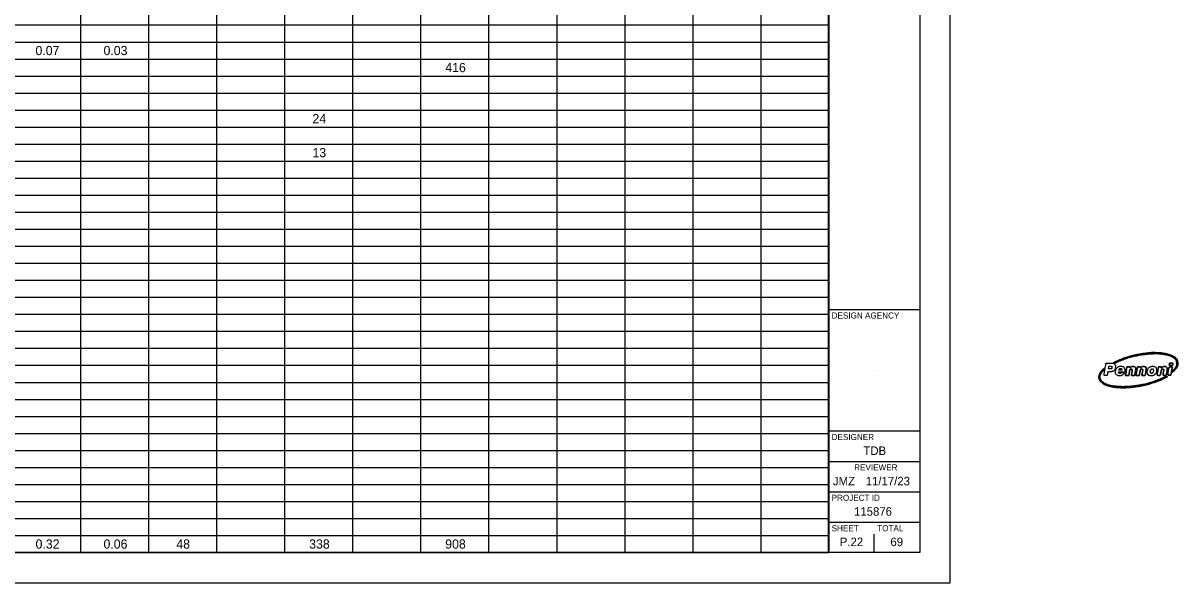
# Model space of a CAD drawing. Extents: x -0.1 to 37.6, y 0 to 22.
# Drawn here: x 18.61 to 37.63, y -0.02 to 9.19 of the extents above; entities that cross this region are included whole.
import ezdxf

# ---------------------------------------------------------------- set-up
doc = ezdxf.new("R2010")
doc.units = 0
for name, color, linetype in [('Default', 7, 'Continuous'), ('SH_Border', 7, 'Continuous'), ('SH_Cut_Line', 7, 'Continuous'), ('SH_Data', 7, 'Continuous')]:
    doc.layers.add(name, color=color, linetype=linetype)

msp = doc.modelspace()

# ---------------------------------------------------------------- linework, layer by layer
at = {"layer": 'Default'}
for p, q in [((19.559, 21.475), (19.559, 0.475)), ((20.679, 21.475), (20.679, 0.475)), ((21.799, 21.475), (21.799, 0.475)), ((22.919, 21.475), (22.919, 0.475)), ((24.039, 21.475), (24.039, 0.475)), ((25.159, 21.475), (25.159, 0.475)), ((26.279, 21.475), (26.279, 0.475)), ((27.399, 21.475), (27.399, 0.475)), ((28.519, 21.475), (28.519, 0.475)), ((29.639, 21.475), (29.639, 0.475)), ((30.759, 21.475), (30.759, 0.475)), ((31.879, 21.475), (31.879, 0.475)), ((1.376, 9.155), (31.879, 9.155)), ((1.376, 8.875), (31.879, 8.875)), ((1.376, 8.595), (31.879, 8.595)), ((1.376, 8.315), (31.879, 8.315)), ((1.376, 8.035), (31.879, 8.035)), ((1.376, 7.755), (31.879, 7.755)), ((1.376, 7.475), (31.879, 7.475)), ((1.376, 7.195), (31.879, 7.195)), ((1.376, 6.915), (31.879, 6.915)), ((1.376, 6.635), (31.879, 6.635)), ((1.376, 6.355), (31.879, 6.355)), ((1.376, 6.075), (31.879, 6.075)), ((1.376, 5.795), (31.879, 5.795)), ((1.376, 5.515), (31.879, 5.515)), ((1.376, 5.235), (31.879, 5.235)), ((1.376, 4.955), (31.879, 4.955)), ((1.376, 4.675), (31.879, 4.675)), ((1.376, 4.395), (31.879, 4.395)), ((1.376, 4.115), (31.879, 4.115)), ((1.376, 3.835), (31.879, 3.835)), ((1.376, 3.555), (31.879, 3.555)), ((1.376, 3.275), (31.879, 3.275)), ((1.376, 2.995), (31.879, 2.995)), ((1.376, 2.715), (31.879, 2.715)), ((1.376, 2.435), (31.879, 2.435)), ((1.376, 2.155), (31.879, 2.155)), ((1.376, 1.875), (31.879, 1.875)), ((1.376, 1.595), (31.879, 1.595)), ((1.376, 1.315), (31.879, 1.315)), ((1.376, 1.035), (31.879, 1.035)), ((1.376, 0.755), (31.879, 0.755)), ((1.376, 0.475), (31.879, 0.475))]:
    msp.add_line(p, q, dxfattribs=at)
at = {"layer": 'SH_Border'}
for p, q in [((31.876, 0.475), (31.876, 21.475)), ((31.876, 4.475), (33.376, 4.475)), ((36.706, 3.478), (36.656, 3.478)), ((31.876, 2.475), (33.376, 2.475)), ((31.876, 1.975), (33.376, 1.975)), ((31.876, 1.475), (33.376, 1.475)), ((31.876, 0.975), (33.376, 0.975))]:
    msp.add_line(p, q, dxfattribs=at)
msp.add_lwpolyline([(1.376, 21.475), (33.376, 21.475), (33.376, 0.475), (1.376, 0.475)], close=True, dxfattribs=at)
for points, degree in [([(36.565, 3.596), (36.572, 3.594), (36.578, 3.591), (36.584, 3.59), (36.586, 3.589), (36.589, 3.589), (36.591, 3.59), (36.62, 3.604), (36.648, 3.618), (36.677, 3.63), (36.718, 3.648), (36.761, 3.663), (36.804, 3.676), (36.846, 3.689), (36.888, 3.7), (36.931, 3.709), (36.971, 3.718), (37.011, 3.726), (37.051, 3.731), (37.083, 3.735), (37.115, 3.739), (37.147, 3.742), (37.173, 3.744), (37.198, 3.745), (37.223, 3.746), (37.278, 3.748), (37.333, 3.745), (37.388, 3.737), (37.417, 3.733), (37.447, 3.727), (37.475, 3.717), (37.511, 3.706), (37.544, 3.692), (37.572, 3.666), (37.588, 3.653), (37.599, 3.636), (37.604, 3.616), (37.609, 3.599), (37.611, 3.582), (37.608, 3.564), (37.604, 3.544), (37.594, 3.527), (37.582, 3.511), (37.57, 3.496), (37.556, 3.483), (37.541, 3.47), (37.54, 3.469), (37.538, 3.467), (37.537, 3.465), (37.536, 3.46), (37.535, 3.454), (37.534, 3.448), (37.534, 3.446), (37.534, 3.444), (37.533, 3.44), (37.557, 3.46), (37.58, 3.48), (37.598, 3.504), (37.607, 3.515), (37.615, 3.528), (37.62, 3.541), (37.627, 3.56), (37.627, 3.579), (37.625, 3.598), (37.621, 3.633), (37.605, 3.66), (37.579, 3.683), (37.555, 3.703), (37.528, 3.716), (37.499, 3.727), (37.461, 3.741), (37.423, 3.749), (37.384, 3.754), (37.349, 3.759), (37.314, 3.762), (37.279, 3.763), (37.222, 3.765), (37.166, 3.762), (37.11, 3.756), (37.079, 3.752), (37.048, 3.748), (37.017, 3.743), (36.972, 3.736), (36.927, 3.727), (36.883, 3.715), (36.822, 3.7), (36.763, 3.682), (36.705, 3.66), (36.664, 3.644), (36.624, 3.626), (36.585, 3.606), (36.578, 3.603), (36.572, 3.6), (36.565, 3.596)], 3), ([(36.565, 3.596), (36.572, 3.6), (36.578, 3.603), (36.585, 3.606), (36.624, 3.626), (36.664, 3.644), (36.705, 3.66), (36.763, 3.682), (36.822, 3.7), (36.883, 3.715), (36.927, 3.727), (36.972, 3.736), (37.017, 3.743), (37.048, 3.748), (37.079, 3.752), (37.11, 3.756), (37.166, 3.762), (37.222, 3.765), (37.279, 3.763), (37.314, 3.762), (37.349, 3.759), (37.384, 3.754), (37.423, 3.749), (37.461, 3.741), (37.499, 3.727), (37.528, 3.716), (37.555, 3.703), (37.579, 3.683), (37.605, 3.66), (37.621, 3.633), (37.625, 3.598), (37.627, 3.579), (37.627, 3.56), (37.62, 3.541), (37.615, 3.528), (37.607, 3.515), (37.598, 3.504), (37.58, 3.48), (37.557, 3.46), (37.533, 3.44), (37.534, 3.444), (37.534, 3.446), (37.534, 3.448), (37.535, 3.454), (37.536, 3.46), (37.537, 3.465), (37.538, 3.467), (37.54, 3.469), (37.541, 3.47), (37.556, 3.483), (37.57, 3.496), (37.582, 3.511), (37.594, 3.527), (37.604, 3.544), (37.608, 3.564), (37.611, 3.582), (37.609, 3.599), (37.604, 3.616), (37.599, 3.636), (37.588, 3.653), (37.572, 3.666), (37.544, 3.692), (37.511, 3.706), (37.475, 3.717), (37.447, 3.727), (37.417, 3.733), (37.388, 3.737), (37.333, 3.745), (37.278, 3.748), (37.223, 3.746), (37.198, 3.745), (37.173, 3.744), (37.147, 3.742), (37.115, 3.739), (37.083, 3.735), (37.051, 3.731), (37.011, 3.726), (36.971, 3.718), (36.931, 3.709), (36.888, 3.7), (36.846, 3.689), (36.804, 3.676), (36.761, 3.663), (36.718, 3.648), (36.677, 3.63), (36.648, 3.618), (36.62, 3.604), (36.591, 3.59), (36.589, 3.589), (36.586, 3.589), (36.584, 3.59), (36.578, 3.591), (36.572, 3.594), (36.565, 3.596)], 3), ([(37.454, 3.367), (37.453, 3.367), (37.453, 3.368), (37.453, 3.368), (37.443, 3.368), (37.433, 3.368), (37.423, 3.368), (37.421, 3.368), (37.418, 3.367), (37.416, 3.366), (37.379, 3.347), (37.341, 3.33), (37.302, 3.315), (37.244, 3.292), (37.184, 3.273), (37.124, 3.258), (37.081, 3.246), (37.038, 3.237), (36.994, 3.229), (36.969, 3.225), (36.944, 3.221), (36.92, 3.218), (36.894, 3.214), (36.868, 3.211), (36.843, 3.209), (36.819, 3.207), (36.794, 3.205), (36.77, 3.205), (36.742, 3.204), (36.714, 3.203), (36.686, 3.205), (36.655, 3.206), (36.624, 3.208), (36.593, 3.211), (36.555, 3.215), (36.517, 3.223), (36.481, 3.234), (36.449, 3.244), (36.419, 3.257), (36.392, 3.277), (36.376, 3.289), (36.362, 3.304), (36.353, 3.323), (36.34, 3.349), (36.342, 3.375), (36.352, 3.402), (36.361, 3.425), (36.375, 3.445), (36.392, 3.463), (36.398, 3.469), (36.403, 3.475), (36.403, 3.484), (36.404, 3.489), (36.405, 3.495), (36.406, 3.501), (36.405, 3.5), (36.404, 3.5), (36.403, 3.499), (36.394, 3.489), (36.384, 3.48), (36.375, 3.469), (36.356, 3.447), (36.34, 3.423), (36.332, 3.394), (36.327, 3.377), (36.326, 3.36), (36.329, 3.343), (36.334, 3.316), (36.348, 3.294), (36.368, 3.276), (36.39, 3.255), (36.417, 3.241), (36.445, 3.229), (36.492, 3.21), (36.542, 3.2), (36.592, 3.194), (36.623, 3.191), (36.654, 3.189), (36.685, 3.187), (36.727, 3.186), (36.769, 3.186), (36.812, 3.19), (36.846, 3.192), (36.88, 3.196), (36.914, 3.2), (36.945, 3.204), (36.976, 3.209), (37.006, 3.214), (37.06, 3.224), (37.114, 3.236), (37.167, 3.252), (37.212, 3.264), (37.257, 3.279), (37.301, 3.296), (37.344, 3.313), (37.386, 3.331), (37.427, 3.353), (37.436, 3.357), (37.445, 3.362), (37.454, 3.367)], 3), ([(37.454, 3.367), (37.445, 3.362), (37.436, 3.357), (37.427, 3.353), (37.386, 3.331), (37.344, 3.313), (37.301, 3.296), (37.257, 3.279), (37.212, 3.264), (37.167, 3.252), (37.114, 3.236), (37.06, 3.224), (37.006, 3.214), (36.976, 3.209), (36.945, 3.204), (36.914, 3.2), (36.88, 3.196), (36.846, 3.192), (36.812, 3.19), (36.769, 3.186), (36.727, 3.186), (36.685, 3.187), (36.654, 3.189), (36.623, 3.191), (36.592, 3.194), (36.542, 3.2), (36.492, 3.21), (36.445, 3.229), (36.417, 3.241), (36.39, 3.255), (36.368, 3.276), (36.348, 3.294), (36.334, 3.316), (36.329, 3.343), (36.326, 3.36), (36.327, 3.377), (36.332, 3.394), (36.34, 3.423), (36.356, 3.447), (36.375, 3.469), (36.384, 3.48), (36.394, 3.489), (36.403, 3.499), (36.404, 3.5), (36.405, 3.5), (36.406, 3.501), (36.405, 3.495), (36.404, 3.489), (36.403, 3.484), (36.403, 3.475), (36.398, 3.469), (36.392, 3.463), (36.375, 3.445), (36.361, 3.425), (36.352, 3.402), (36.342, 3.375), (36.34, 3.349), (36.353, 3.323), (36.362, 3.304), (36.376, 3.289), (36.392, 3.277), (36.419, 3.257), (36.449, 3.244), (36.481, 3.234), (36.517, 3.223), (36.555, 3.215), (36.593, 3.211), (36.624, 3.208), (36.655, 3.206), (36.686, 3.205), (36.714, 3.203), (36.742, 3.204), (36.77, 3.205), (36.794, 3.205), (36.819, 3.207), (36.843, 3.209), (36.868, 3.211), (36.894, 3.214), (36.92, 3.218), (36.944, 3.221), (36.969, 3.225), (36.994, 3.229), (37.038, 3.237), (37.081, 3.246), (37.124, 3.258), (37.184, 3.273), (37.244, 3.292), (37.302, 3.315), (37.341, 3.33), (37.379, 3.347), (37.416, 3.366), (37.418, 3.367), (37.421, 3.368), (37.423, 3.368), (37.433, 3.368), (37.443, 3.368), (37.453, 3.368), (37.453, 3.368), (37.453, 3.367), (37.454, 3.367)], 3), ([(36.577, 3.577), (36.564, 3.583), (36.551, 3.585), (36.537, 3.585), (36.505, 3.586), (36.474, 3.585), (36.442, 3.586), (36.44, 3.586), (36.439, 3.585), (36.438, 3.583), (36.435, 3.561), (36.431, 3.54), (36.427, 3.518), (36.421, 3.484), (36.415, 3.449), (36.409, 3.414), (36.408, 3.407), (36.406, 3.399), (36.405, 3.392)], 3), ([(36.405, 3.392), (36.406, 3.392), (36.407, 3.392), (36.407, 3.392), (36.427, 3.392), (36.446, 3.392), (36.465, 3.392), (36.468, 3.392), (36.468, 3.393), (36.468, 3.395), (36.47, 3.406), (36.472, 3.417), (36.474, 3.429), (36.476, 3.437), (36.477, 3.444), (36.478, 3.452)], 3), ([(36.478, 3.452), (36.486, 3.452), (36.493, 3.452), (36.5, 3.452), (36.513, 3.452), (36.526, 3.452), (36.539, 3.455), (36.555, 3.458), (36.57, 3.465), (36.582, 3.477), (36.597, 3.493), (36.603, 3.512), (36.603, 3.534), (36.604, 3.553), (36.595, 3.568), (36.577, 3.577)], 3), ([(36.486, 3.497), (36.489, 3.511), (36.491, 3.525), (36.494, 3.538), (36.494, 3.539), (36.495, 3.54), (36.496, 3.54), (36.507, 3.54), (36.519, 3.542), (36.53, 3.538), (36.54, 3.535), (36.544, 3.529), (36.542, 3.518)], 3), ([(36.542, 3.518), (36.54, 3.506), (36.531, 3.498), (36.518, 3.497), (36.508, 3.497), (36.497, 3.497), (36.486, 3.497)], 3), ([(36.758, 3.483), (36.754, 3.508), (36.741, 3.525), (36.717, 3.532), (36.704, 3.537), (36.691, 3.537), (36.677, 3.536), (36.655, 3.533), (36.636, 3.524), (36.62, 3.507), (36.606, 3.493), (36.599, 3.475), (36.596, 3.454), (36.593, 3.425), (36.605, 3.401), (36.635, 3.392), (36.651, 3.387), (36.667, 3.387), (36.683, 3.389), (36.701, 3.391), (36.717, 3.397), (36.731, 3.409), (36.739, 3.416), (36.745, 3.424), (36.749, 3.434)], 3), ([(36.749, 3.434), (36.732, 3.434), (36.715, 3.434), (36.699, 3.434), (36.697, 3.434), (36.696, 3.433), (36.695, 3.432), (36.691, 3.429), (36.687, 3.425), (36.683, 3.423), (36.667, 3.417), (36.649, 3.426), (36.65, 3.445), (36.65, 3.449), (36.651, 3.45), (36.655, 3.45), (36.687, 3.45), (36.72, 3.45), (36.752, 3.45), (36.753, 3.45), (36.755, 3.45), (36.757, 3.45)], 3), ([(36.656, 3.478), (36.657, 3.49), (36.667, 3.5), (36.679, 3.502), (36.685, 3.503), (36.691, 3.503), (36.697, 3.5), (36.704, 3.496), (36.708, 3.488), (36.706, 3.478)], 3), ([(36.757, 3.45), (36.759, 3.461), (36.76, 3.472), (36.758, 3.483)], 2), ([(36.764, 3.391), (36.765, 3.39), (36.765, 3.39), (36.766, 3.39), (36.783, 3.39), (36.8, 3.39), (36.817, 3.39), (36.819, 3.39), (36.82, 3.392), (36.82, 3.393), (36.821, 3.401), (36.823, 3.41), (36.824, 3.418), (36.827, 3.435), (36.83, 3.453), (36.834, 3.471), (36.836, 3.48), (36.841, 3.488), (36.851, 3.49), (36.864, 3.494), (36.877, 3.491), (36.875, 3.472), (36.873, 3.457), (36.87, 3.443), (36.868, 3.429), (36.866, 3.416), (36.864, 3.404), (36.861, 3.391), (36.862, 3.39), (36.863, 3.39), (36.863, 3.39), (36.88, 3.39), (36.897, 3.39), (36.914, 3.39), (36.917, 3.39), (36.917, 3.392), (36.917, 3.394), (36.921, 3.418), (36.926, 3.441), (36.93, 3.465), (36.932, 3.478), (36.934, 3.49), (36.933, 3.502), (36.931, 3.518), (36.921, 3.53), (36.905, 3.533), (36.884, 3.539), (36.864, 3.535), (36.847, 3.52), (36.843, 3.517), (36.84, 3.513), (36.835, 3.51), (36.837, 3.517), (36.838, 3.524), (36.839, 3.532), (36.823, 3.532), (36.807, 3.532), (36.79, 3.531), (36.79, 3.531), (36.788, 3.53), (36.788, 3.529), (36.787, 3.525), (36.786, 3.521), (36.786, 3.516), (36.78, 3.486), (36.775, 3.455), (36.77, 3.425), (36.768, 3.413), (36.766, 3.402), (36.764, 3.391)], 3), ([(36.764, 3.391), (36.766, 3.402), (36.768, 3.413), (36.77, 3.425), (36.775, 3.455), (36.78, 3.486), (36.786, 3.516), (36.786, 3.521), (36.787, 3.525), (36.788, 3.529), (36.788, 3.53), (36.79, 3.531), (36.79, 3.531), (36.807, 3.532), (36.823, 3.532), (36.839, 3.532), (36.838, 3.524), (36.837, 3.517), (36.835, 3.51), (36.84, 3.513), (36.843, 3.517), (36.847, 3.52), (36.864, 3.535), (36.884, 3.539), (36.905, 3.533), (36.921, 3.53), (36.931, 3.518), (36.933, 3.502), (36.934, 3.49), (36.932, 3.478), (36.93, 3.465), (36.926, 3.441), (36.921, 3.418), (36.917, 3.394), (36.917, 3.392), (36.917, 3.39), (36.914, 3.39), (36.897, 3.39), (36.88, 3.39), (36.863, 3.39), (36.863, 3.39), (36.862, 3.39), (36.861, 3.391), (36.864, 3.404), (36.866, 3.416), (36.868, 3.429), (36.87, 3.443), (36.873, 3.457), (36.875, 3.472), (36.877, 3.491), (36.864, 3.494), (36.851, 3.49), (36.841, 3.488), (36.836, 3.48), (36.834, 3.471), (36.83, 3.453), (36.827, 3.435), (36.824, 3.418), (36.823, 3.41), (36.821, 3.401), (36.82, 3.393), (36.82, 3.392), (36.819, 3.39), (36.817, 3.39), (36.8, 3.39), (36.783, 3.39), (36.766, 3.39), (36.765, 3.39), (36.765, 3.39), (36.764, 3.391)], 3), ([(36.937, 3.391), (36.937, 3.39), (36.938, 3.39), (36.938, 3.39), (36.955, 3.39), (36.973, 3.39), (36.99, 3.39), (36.991, 3.39), (36.993, 3.392), (36.993, 3.393), (36.996, 3.41), (36.999, 3.427), (37.002, 3.444), (37.004, 3.454), (37.005, 3.465), (37.008, 3.475), (37.012, 3.488), (37.024, 3.494), (37.037, 3.491), (37.043, 3.49), (37.047, 3.486), (37.048, 3.48), (37.048, 3.477), (37.048, 3.474), (37.048, 3.471), (37.046, 3.46), (37.044, 3.448), (37.042, 3.437), (37.04, 3.422), (37.037, 3.406), (37.034, 3.391), (37.035, 3.391), (37.035, 3.39), (37.035, 3.39), (37.053, 3.39), (37.07, 3.39), (37.088, 3.39), (37.088, 3.39), (37.09, 3.392), (37.09, 3.393), (37.094, 3.416), (37.098, 3.438), (37.102, 3.46), (37.104, 3.472), (37.106, 3.484), (37.106, 3.497), (37.106, 3.512), (37.1, 3.525), (37.084, 3.531), (37.064, 3.539), (37.044, 3.537), (37.026, 3.525), (37.02, 3.52), (37.015, 3.515), (37.009, 3.51), (37.01, 3.518), (37.011, 3.524), (37.012, 3.532), (36.996, 3.532), (36.98, 3.532), (36.964, 3.532), (36.961, 3.532), (36.961, 3.53), (36.961, 3.528), (36.957, 3.504), (36.953, 3.48), (36.948, 3.457), (36.945, 3.435), (36.941, 3.413), (36.937, 3.391)], 3), ([(36.937, 3.391), (36.941, 3.413), (36.945, 3.435), (36.948, 3.457), (36.953, 3.48), (36.957, 3.504), (36.961, 3.528), (36.961, 3.53), (36.961, 3.532), (36.964, 3.532), (36.98, 3.532), (36.996, 3.532), (37.012, 3.532), (37.011, 3.524), (37.01, 3.518), (37.009, 3.51), (37.015, 3.515), (37.02, 3.52), (37.026, 3.525), (37.044, 3.537), (37.064, 3.539), (37.084, 3.531), (37.1, 3.525), (37.106, 3.512), (37.106, 3.497), (37.106, 3.484), (37.104, 3.472), (37.102, 3.46), (37.098, 3.438), (37.094, 3.416), (37.09, 3.393), (37.09, 3.392), (37.088, 3.39), (37.088, 3.39), (37.07, 3.39), (37.053, 3.39), (37.035, 3.39), (37.035, 3.39), (37.035, 3.391), (37.034, 3.391), (37.037, 3.406), (37.04, 3.422), (37.042, 3.437), (37.044, 3.448), (37.046, 3.46), (37.048, 3.471), (37.048, 3.474), (37.048, 3.477), (37.048, 3.48), (37.047, 3.486), (37.043, 3.49), (37.037, 3.491), (37.024, 3.494), (37.012, 3.488), (37.008, 3.475), (37.005, 3.465), (37.004, 3.454), (37.002, 3.444), (36.999, 3.427), (36.996, 3.41), (36.993, 3.393), (36.993, 3.392), (36.991, 3.39), (36.99, 3.39), (36.973, 3.39), (36.955, 3.39), (36.938, 3.39), (36.938, 3.39), (36.937, 3.39), (36.937, 3.391)], 3), ([(37.28, 3.483), (37.279, 3.505), (37.267, 3.521), (37.247, 3.529), (37.228, 3.537), (37.208, 3.537), (37.188, 3.533), (37.164, 3.528), (37.145, 3.516), (37.132, 3.495), (37.13, 3.493), (37.129, 3.49), (37.128, 3.488), (37.127, 3.486), (37.126, 3.484), (37.125, 3.482), (37.12, 3.471), (37.117, 3.459), (37.117, 3.447), (37.117, 3.445), (37.117, 3.442), (37.117, 3.44), (37.117, 3.432), (37.119, 3.425), (37.122, 3.419), (37.122, 3.418), (37.123, 3.416), (37.123, 3.415), (37.124, 3.414), (37.125, 3.413), (37.125, 3.412), (37.128, 3.409), (37.131, 3.405), (37.134, 3.402), (37.136, 3.401), (37.138, 3.399), (37.14, 3.398), (37.141, 3.397), (37.141, 3.397), (37.142, 3.397), (37.143, 3.396), (37.144, 3.395), (37.145, 3.395), (37.147, 3.394), (37.149, 3.393), (37.151, 3.392), (37.162, 3.388), (37.174, 3.386), (37.186, 3.386)], 3), ([(37.173, 3.446), (37.174, 3.463), (37.176, 3.476), (37.185, 3.488), (37.19, 3.494), (37.197, 3.498), (37.205, 3.498), (37.214, 3.498), (37.22, 3.495), (37.222, 3.486), (37.224, 3.48), (37.224, 3.473), (37.224, 3.466)], 3), ([(37.224, 3.466), (37.223, 3.456), (37.22, 3.446), (37.215, 3.437), (37.209, 3.427), (37.199, 3.422), (37.189, 3.424), (37.182, 3.425), (37.178, 3.428), (37.175, 3.435), (37.174, 3.439), (37.173, 3.444), (37.173, 3.446)], 3), ([(37.186, 3.386), (37.193, 3.386), (37.2, 3.387), (37.207, 3.388), (37.226, 3.392), (37.243, 3.4), (37.256, 3.414), (37.274, 3.434), (37.281, 3.457), (37.28, 3.483)], 3), ([(37.308, 3.531), (37.299, 3.484), (37.291, 3.438), (37.283, 3.39), (37.302, 3.39), (37.32, 3.39), (37.338, 3.39), (37.341, 3.405), (37.343, 3.419), (37.346, 3.433), (37.348, 3.446), (37.35, 3.459), (37.353, 3.471), (37.356, 3.485), (37.366, 3.492), (37.38, 3.492), (37.388, 3.491), (37.393, 3.487), (37.394, 3.478), (37.394, 3.475), (37.394, 3.472), (37.394, 3.469), (37.391, 3.45), (37.387, 3.431), (37.384, 3.412), (37.383, 3.405), (37.382, 3.398), (37.38, 3.39), (37.399, 3.39), (37.417, 3.39), (37.436, 3.39), (37.436, 3.392), (37.436, 3.393), (37.437, 3.394), (37.44, 3.415), (37.444, 3.437), (37.448, 3.458), (37.45, 3.472), (37.453, 3.485), (37.452, 3.5), (37.451, 3.516), (37.442, 3.528), (37.426, 3.533), (37.402, 3.54), (37.38, 3.534), (37.361, 3.516), (37.359, 3.514), (37.357, 3.512), (37.355, 3.51), (37.355, 3.51), (37.355, 3.51), (37.355, 3.511), (37.356, 3.517), (37.357, 3.524), (37.358, 3.531), (37.341, 3.531), (37.325, 3.531), (37.308, 3.531)], 3), ([(37.308, 3.531), (37.325, 3.531), (37.341, 3.531), (37.358, 3.531), (37.357, 3.524), (37.356, 3.517), (37.355, 3.511), (37.355, 3.51), (37.355, 3.51), (37.355, 3.51), (37.357, 3.512), (37.359, 3.514), (37.361, 3.516), (37.38, 3.534), (37.402, 3.54), (37.426, 3.533), (37.442, 3.528), (37.451, 3.516), (37.452, 3.5), (37.453, 3.485), (37.45, 3.472), (37.448, 3.458), (37.444, 3.437), (37.44, 3.415), (37.437, 3.394), (37.436, 3.393), (37.436, 3.392), (37.436, 3.39), (37.417, 3.39), (37.399, 3.39), (37.38, 3.39), (37.382, 3.398), (37.383, 3.405), (37.384, 3.412), (37.387, 3.431), (37.391, 3.45), (37.394, 3.469), (37.394, 3.472), (37.394, 3.475), (37.394, 3.478), (37.393, 3.487), (37.388, 3.491), (37.38, 3.492), (37.366, 3.492), (37.356, 3.485), (37.353, 3.471), (37.35, 3.459), (37.348, 3.446), (37.346, 3.433), (37.343, 3.419), (37.341, 3.405), (37.338, 3.39), (37.32, 3.39), (37.302, 3.39), (37.283, 3.39), (37.291, 3.438), (37.299, 3.484), (37.308, 3.531)], 3), ([(37.51, 3.392), (37.492, 3.392), (37.474, 3.392), (37.455, 3.392), (37.463, 3.439), (37.471, 3.485), (37.48, 3.532), (37.498, 3.532), (37.516, 3.532), (37.535, 3.532), (37.527, 3.485), (37.519, 3.439), (37.51, 3.392)], 3), ([(37.51, 3.392), (37.519, 3.439), (37.527, 3.485), (37.535, 3.532), (37.516, 3.532), (37.498, 3.532), (37.48, 3.532), (37.471, 3.485), (37.463, 3.439), (37.455, 3.392), (37.474, 3.392), (37.492, 3.392), (37.51, 3.392)], 3), ([(37.545, 3.59), (37.543, 3.578), (37.541, 3.566), (37.539, 3.553), (37.538, 3.553), (37.537, 3.551), (37.536, 3.551), (37.518, 3.551), (37.501, 3.551), (37.483, 3.551), (37.485, 3.561), (37.486, 3.57), (37.488, 3.579), (37.488, 3.581), (37.489, 3.584), (37.489, 3.586), (37.489, 3.59), (37.491, 3.591), (37.494, 3.591), (37.51, 3.59), (37.525, 3.59), (37.541, 3.59), (37.542, 3.59), (37.543, 3.59), (37.545, 3.59)], 3), ([(37.545, 3.59), (37.543, 3.59), (37.542, 3.59), (37.541, 3.59), (37.525, 3.59), (37.51, 3.59), (37.494, 3.591), (37.491, 3.591), (37.489, 3.59), (37.489, 3.586), (37.489, 3.584), (37.488, 3.581), (37.488, 3.579), (37.486, 3.57), (37.485, 3.561), (37.483, 3.551), (37.501, 3.551), (37.518, 3.551), (37.536, 3.551), (37.537, 3.551), (37.538, 3.553), (37.539, 3.553), (37.541, 3.566), (37.543, 3.578), (37.545, 3.59)], 3)]:
    msp.add_open_spline(points, degree=degree, dxfattribs=at)
at = {"layer": 'SH_Cut_Line'}
msp.add_lwpolyline([(-0.124, -0.025), (33.876, -0.025), (33.876, 21.975), (-0.124, 21.975)], close=True, dxfattribs=at)
at = {"layer": 'SH_Data'}
for p, q in [((32.626, 3.475), (32.626, 3.475)), ((32.626, 0.475), (32.626, 0.775)), ((32.251, 0.65), (32.251, 0.65))]:
    msp.add_line(p, q, dxfattribs=at)

# ---------------------------------------------------------------- texts
at = {"layer": 'Default'}
for s, p in [('0.07', (18.818, 8.659)), ('0.03', (19.938, 8.659)), ('416', (25.565, 8.379)), ('24', (23.378, 7.539)), ('13', (23.378, 6.979)), ('0.32', (18.819, 0.539)), ('0.06', (19.938, 0.539)), ('48', (21.137, 0.539)), ('338', (23.324, 0.539)), ('908', (25.564, 0.539))]:
    msp.add_text(s, height=0.1515, dxfattribs=at).set_placement(p)
at = {"layer": 'SH_Data'}
for s, height, p in [('DESIGN AGENCY', 0.1, (31.926, 4.325)), ('DESIGNER', 0.1, (31.926, 2.325)), ('TDB', 0.14, (32.449, 2.08)), ('REVIEWER', 0.1, (32.297, 1.825)), ('JMZ', 0.14, (31.947, 1.58)), ('11/17/23', 0.14, (32.487, 1.58)), ('PROJECT ID', 0.1, (31.926, 1.325)), ('115876', 0.14, (32.295, 1.08)), ('SHEET', 0.1, (31.926, 0.825)), ('TOTAL', 0.1, (32.676, 0.825)), ('P.22', 0.14, (32.06, 0.58)), ('69', 0.14, (32.894, 0.58))]:
    msp.add_text(s, height=height, dxfattribs=at).set_placement(p)

doc.saveas('drawing.dxf')
